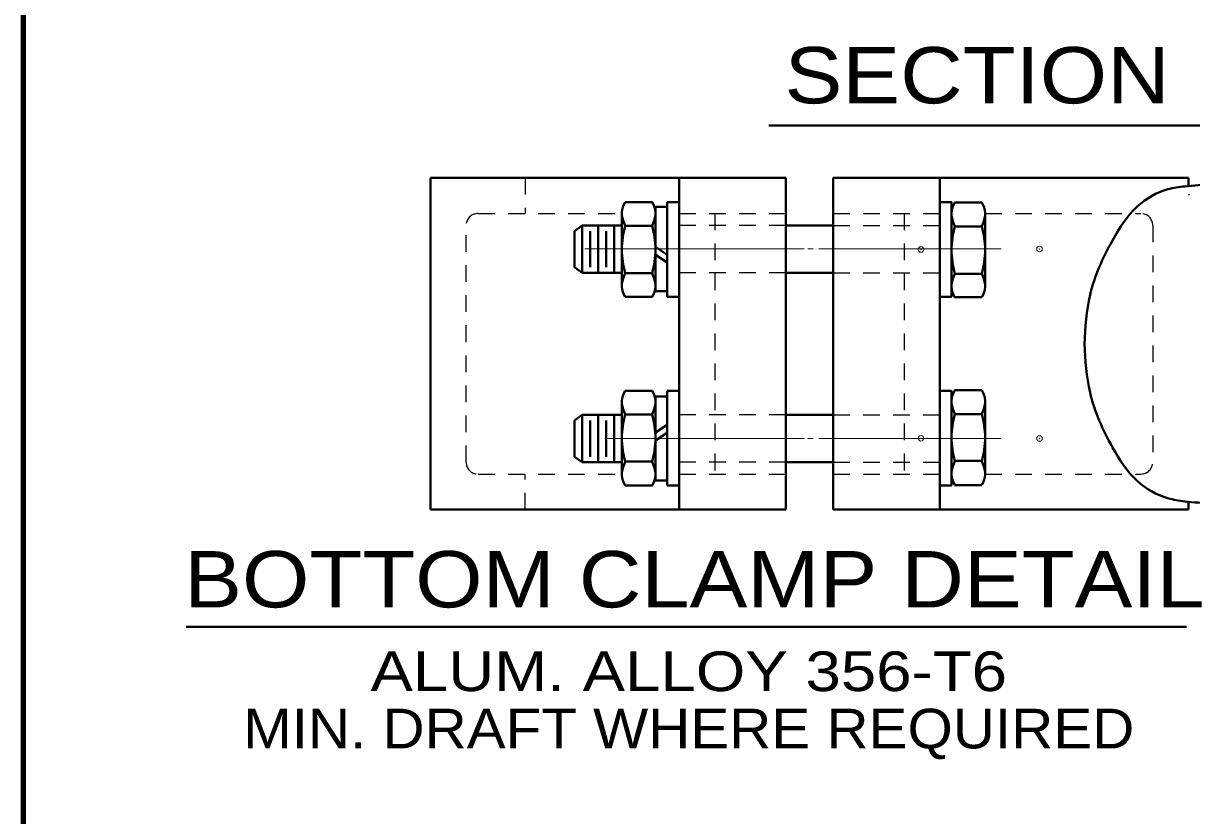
# Model space of a CAD drawing. Extents: x 312583 to 312854, y 144419 to 144597.
# Drawn here: x 312616.5 to 312648.02, y 144524.12 to 144545.49 of the extents above; entities that cross this region are included whole.
import ezdxf
from ezdxf.enums import TextEntityAlignment as Align

# ---------------------------------------------------------------- set-up
doc = ezdxf.new("R2010")
doc.units = 0
doc.header["$LTSCALE"] = 0.3
doc.header["$PDMODE"] = 32
doc.header["$PDSIZE"] = 0.15
doc.linetypes.add('SHORT_DASHED', pattern=[2.7, 1.5, -1.2])
doc.layers.add('1', color=7, linetype='Continuous', lineweight=35)
doc.layers.add('2', color=7, linetype='Continuous', lineweight=13)

msp = doc.modelspace()

# ---------------------------------------------------------------- linework, layer by layer
at = {"layer": '1', "lineweight": 40}
for p, q in [((312627.4877, 144536.8489), (312627.4877, 144541.3263)), ((312634.196, 144536.8489), (312634.196, 144541.3263)), ((312637.071, 144536.8489), (312637.071, 144541.3263)), ((312638.3513, 144536.8489), (312638.3513, 144541.3263)), ((312641.2263, 144536.8489), (312641.2263, 144541.3263)), ((312647.9347, 144541.1039), (312647.9347, 144541.3263)), ((312633.4753, 144540.6746), (312632.7393, 144540.6746)), ((312633.874, 144540.6746), (312633.874, 144538.1216)), ((312633.874, 144540.6746), (312634.196, 144540.6746)), ((312634.196, 144540.6746), (312634.196, 144538.1216)), ((312641.2263, 144538.1216), (312641.2263, 144540.6746)), ((312641.625, 144540.6593), (312642.361, 144540.6593)), ((312632.6473, 144540.3909), (312632.6473, 144539.4019)), ((312633.5597, 144540.3986), (312633.5597, 144540.5443)), ((312633.5597, 144540.5443), (312633.5597, 144538.2673)), ((312633.5597, 144540.5443), (312633.874, 144540.5443)), ((312633.5597, 144540.3986), (312633.5597, 144539.4096)), ((312641.5407, 144540.3833), (312641.5407, 144539.3943)), ((312642.453, 144540.3756), (312642.453, 144539.3943)), ((312632.6473, 144540.0459), (312631.5817, 144540.0459)), ((312632.011, 144540.0459), (312632.011, 144539.4019)), ((312632.4403, 144540.0459), (312632.4403, 144539.4019)), ((312633.4753, 144540.0306), (312632.7393, 144540.0306)), ((312638.3513, 144540.0459), (312637.071, 144540.0459)), ((312641.625, 144540.0153), (312642.361, 144540.0153)), ((312631.367, 144539.8926), (312631.367, 144539.4019)), ((312631.7963, 144539.8926), (312631.7963, 144539.4019)), ((312632.2257, 144539.8926), (312632.2257, 144539.4019)), ((312631.367, 144538.9189), (312631.367, 144539.4096)), ((312631.7963, 144538.9189), (312631.7963, 144539.4096)), ((312632.011, 144538.7656), (312632.011, 144539.4096)), ((312632.2257, 144538.9189), (312632.2257, 144539.4096)), ((312632.4403, 144538.7656), (312632.4403, 144539.4096)), ((312632.6473, 144538.3976), (312632.6473, 144539.4096)), ((312633.5597, 144539.4633), (312633.874, 144539.2486)), ((312633.5597, 144538.3976), (312633.5597, 144539.4096)), ((312641.5407, 144538.3823), (312641.5407, 144539.3943)), ((312642.453, 144538.3899), (312642.453, 144539.4019)), ((312633.5597, 144539.2486), (312633.874, 144539.0416)), ((312632.6473, 144538.7656), (312631.5817, 144538.7656)), ((312633.4677, 144538.7579), (312632.7393, 144538.7579)), ((312638.3513, 144538.7656), (312637.071, 144538.7656)), ((312641.6327, 144538.7426), (312642.361, 144538.7426)), ((312633.5597, 144538.2673), (312633.5597, 144538.3976)), ((312633.4753, 144538.1216), (312632.7393, 144538.1216)), ((312633.5597, 144538.2673), (312633.874, 144538.2673)), ((312633.874, 144538.1216), (312634.196, 144538.1216)), ((312641.5407, 144538.1216), (312641.2263, 144538.1216)), ((312641.625, 144538.1063), (312642.361, 144538.1063)), ((312627.4877, 144536.8489), (312627.4877, 144532.3793)), ((312634.196, 144536.8489), (312634.196, 144532.3793)), ((312637.071, 144536.8489), (312637.071, 144532.3793)), ((312638.3513, 144536.8489), (312638.3513, 144532.3793)), ((312641.2263, 144536.8489), (312641.2263, 144532.3793)), ((312633.4753, 144535.5839), (312632.7393, 144535.5839)), ((312633.874, 144535.5839), (312634.196, 144535.5839)), ((312633.874, 144533.0309), (312633.874, 144535.5839)), ((312634.196, 144533.0309), (312634.196, 144535.5839)), ((312641.5407, 144535.5839), (312641.2263, 144535.5839)), ((312641.2263, 144535.5839), (312641.2263, 144533.0309)), ((312641.625, 144535.5993), (312642.361, 144535.5993)), ((312632.6473, 144535.3003), (312632.6473, 144534.2883)), ((312633.5597, 144535.4306), (312633.5597, 144535.3079)), ((312633.5597, 144535.4306), (312633.874, 144535.4306)), ((312633.5597, 144533.1613), (312633.5597, 144535.4306)), ((312633.5597, 144535.3079), (312633.5597, 144534.2959)), ((312641.5407, 144535.3156), (312641.5407, 144534.3036)), ((312642.453, 144535.3156), (312642.453, 144534.3036)), ((312632.6473, 144534.9323), (312631.5817, 144534.9323)), ((312632.011, 144534.9323), (312632.011, 144534.2883)), ((312632.4403, 144534.9323), (312632.4403, 144534.2883)), ((312633.4677, 144534.9476), (312632.7393, 144534.9476)), ((312638.3513, 144534.9323), (312637.071, 144534.9323)), ((312641.6327, 144534.9553), (312642.361, 144534.9553)), ((312631.367, 144534.7866), (312631.367, 144534.2883)), ((312631.7963, 144534.7866), (312631.7963, 144534.2883)), ((312632.2257, 144534.7866), (312632.2257, 144534.2883)), ((312633.5597, 144534.4569), (312633.874, 144534.6639)), ((312631.367, 144533.8053), (312631.367, 144534.3036)), ((312631.7963, 144533.8053), (312631.7963, 144534.3036)), ((312632.011, 144533.6596), (312632.011, 144534.3036)), ((312632.2257, 144533.8053), (312632.2257, 144534.3036)), ((312632.4403, 144533.6596), (312632.4403, 144534.3036)), ((312632.6473, 144533.3146), (312632.6473, 144534.2959)), ((312633.5597, 144534.2423), (312633.874, 144534.4493)), ((312633.5597, 144533.3069), (312633.5597, 144534.2959)), ((312641.5407, 144533.3223), (312641.5407, 144534.3036)), ((312642.453, 144533.3223), (312642.453, 144534.3113)), ((312632.6473, 144533.6596), (312631.5817, 144533.6596)), ((312633.4753, 144533.6749), (312632.7393, 144533.6749)), ((312638.3513, 144533.6596), (312637.071, 144533.6596)), ((312641.625, 144533.6903), (312642.361, 144533.6903)), ((312633.5597, 144533.3069), (312633.5597, 144533.1613)), ((312633.4753, 144533.0309), (312632.7393, 144533.0309)), ((312633.5597, 144533.1613), (312633.874, 144533.1613)), ((312633.874, 144533.0309), (312634.196, 144533.0309)), ((312641.625, 144533.0386), (312642.361, 144533.0386)), ((312647.9347, 144532.5939), (312647.9347, 144532.3793))]:
    msp.add_line(p, q, dxfattribs=at)
at = {"layer": '1', "linetype": 'SHORT_DASHED', "lineweight": 25}
for p, q in [((312630.0407, 144541.3263), (312630.0407, 144540.3679)), ((312628.768, 144540.3679), (312632.6473, 144540.3679)), ((312634.196, 144540.3679), (312637.071, 144540.3679)), ((312635.1543, 144540.3679), (312635.1543, 144533.3376)), ((312638.3513, 144540.3679), (312641.2263, 144540.3679)), ((312640.268, 144540.3679), (312640.268, 144533.3376)), ((312642.453, 144540.3679), (312646.6543, 144540.3679)), ((312628.446, 144533.6596), (312628.446, 144540.0459)), ((312637.071, 144540.0459), (312634.196, 144540.0459)), ((312638.3513, 144540.0459), (312641.2263, 144540.0459)), ((312646.9763, 144540.0459), (312646.9763, 144533.6596)), ((312637.071, 144538.7656), (312634.196, 144538.7656)), ((312638.3513, 144538.7656), (312641.2263, 144538.7656)), ((312637.071, 144534.9323), (312634.196, 144534.9323)), ((312638.3513, 144534.9323), (312641.2263, 144534.9323)), ((312637.071, 144533.6596), (312634.196, 144533.6596)), ((312638.3513, 144533.6596), (312641.2263, 144533.6596)), ((312628.768, 144533.3376), (312632.6473, 144533.3376)), ((312630.0407, 144532.3793), (312630.0407, 144533.3376)), ((312634.196, 144533.3376), (312637.071, 144533.3376)), ((312638.3513, 144533.3376), (312641.2263, 144533.3376)), ((312642.453, 144533.3376), (312646.6543, 144533.3376))]:
    msp.add_line(p, q, dxfattribs=at)
at = {"layer": '1', "lineweight": 25}
msp.add_line((312647.9347, 144540.8586), (312647.9653, 144540.8893), dxfattribs=at)
at = {"layer": '1', "lineweight": 158}
msp.add_lwpolyline([(312616.5, 144423.1446), (312616.5, 144585.0846), (312849, 144585.0846)], dxfattribs=at)
at = {"layer": '1', "lineweight": 40}
for points in [[(312627.4877, 144541.3263), (312634.196, 144541.3263), (312637.071, 144541.3263)], [(312647.9347, 144541.3263), (312641.2263, 144541.3263), (312638.3513, 144541.3263)], [(312641.5407, 144538.1216), (312641.5407, 144540.6746), (312641.2263, 144540.6746)], [(312631.367, 144539.8926), (312631.5817, 144540.0459), (312631.5817, 144539.4019)], [(312631.367, 144538.9189), (312631.5817, 144538.7656), (312631.5817, 144539.4096)], [(312641.5407, 144535.5839), (312641.5407, 144533.0309), (312641.2263, 144533.0309)], [(312631.367, 144534.7866), (312631.5817, 144534.9323), (312631.5817, 144534.2883)], [(312631.367, 144533.8053), (312631.5817, 144533.6596), (312631.5817, 144534.3036)], [(312627.4877, 144532.3793), (312634.196, 144532.3793), (312637.071, 144532.3793)], [(312647.9347, 144532.3793), (312641.2263, 144532.3793), (312638.3513, 144532.3793)]]:
    msp.add_lwpolyline(points, dxfattribs=at)
for centre, radius, start, end in [((312633.1751, 144540.3759), 0.5262, 145.8703, 178.33743), ((312633.0301, 144540.3759), 0.5262, 1.66257, 34.1297), ((312642.0702, 144540.3631), 0.5262, 145.8703, 178.33743), ((312641.9253, 144540.3631), 0.5262, 1.66257, 34.1297), ((312634.1227, 144540.63), 1.5067, 191.77014, 203.36365), ((312632.0825, 144540.63), 1.5067, 336.63635, 348.22986), ((312643.0179, 144540.6172), 1.5067, 191.77014, 203.36365), ((312640.9776, 144540.6172), 1.5067, 336.63635, 348.22986), ((312635.366, 144539.3286), 2.7192, 164.99798, 178.595), ((312630.8392, 144539.3286), 2.7192, 1.405, 15.00202), ((312644.2612, 144539.3158), 2.7192, 164.99798, 178.595), ((312639.7343, 144539.3158), 2.7192, 1.405, 15.00202), ((312635.366, 144539.462), 2.7192, 181.405, 195.00202), ((312630.8392, 144539.462), 2.7192, 344.99798, 358.595), ((312644.2612, 144539.4492), 2.7192, 181.405, 195.00202), ((312639.7343, 144539.4492), 2.7192, 344.99798, 358.595), ((312634.1227, 144538.1606), 1.5067, 156.63635, 168.22986), ((312632.0825, 144538.1606), 1.5067, 11.77014, 23.36365), ((312643.0179, 144538.1478), 1.5067, 156.63635, 168.22986), ((312640.9776, 144538.1478), 1.5067, 11.77014, 23.36365), ((312633.1751, 144538.4147), 0.5262, 181.66257, 214.1297), ((312633.0301, 144538.4147), 0.5262, 325.8703, 358.33743), ((312642.0702, 144538.4019), 0.5262, 181.66257, 214.1297), ((312641.9253, 144538.4019), 0.5262, 325.8703, 358.33743), ((312633.1751, 144535.2883), 0.5262, 145.8703, 178.33743), ((312633.0301, 144535.2883), 0.5262, 1.66257, 34.1297), ((312642.0702, 144535.3011), 0.5262, 145.8703, 178.33743), ((312641.9253, 144535.3011), 0.5262, 1.66257, 34.1297), ((312634.1227, 144535.5424), 1.5067, 191.77014, 203.36365), ((312632.0825, 144535.5424), 1.5067, 336.63635, 348.22986), ((312643.0179, 144535.5552), 1.5067, 191.77014, 203.36365), ((312640.9776, 144535.5552), 1.5067, 336.63635, 348.22986), ((312635.366, 144534.241), 2.7192, 164.99798, 178.595), ((312630.8392, 144534.241), 2.7192, 1.405, 15.00202), ((312644.2612, 144534.2538), 2.7192, 164.99798, 178.595), ((312639.7343, 144534.2538), 2.7192, 1.405, 15.00202), ((312635.366, 144534.3744), 2.7192, 181.405, 195.00202), ((312630.8392, 144534.3744), 2.7192, 344.99798, 358.595), ((312644.2612, 144534.3871), 2.7192, 181.405, 195.00202), ((312639.7343, 144534.3871), 2.7192, 344.99798, 358.595), ((312634.1227, 144533.073), 1.5067, 156.63635, 168.22986), ((312632.0825, 144533.073), 1.5067, 11.77014, 23.36365), ((312643.0179, 144533.0858), 1.5067, 156.63635, 168.22986), ((312640.9776, 144533.0858), 1.5067, 11.77014, 23.36365), ((312633.1751, 144533.3271), 0.5262, 181.66257, 214.1297), ((312633.0301, 144533.3271), 0.5262, 325.8703, 358.33743), ((312642.0702, 144533.3398), 0.5262, 181.66257, 214.1297), ((312641.9253, 144533.3398), 0.5262, 325.8703, 358.33743)]:
    msp.add_arc(centre, radius, start, end, dxfattribs=at)
at = {"layer": '1', "linetype": 'SHORT_DASHED', "lineweight": 25}
for centre, start, end in [((312628.7654, 144540.0459), 90, 180), ((312646.6543, 144540.0459), 0, 90), ((312628.7654, 144533.657), 180, 270), ((312646.6543, 144533.657), 270, 0)]:
    msp.add_arc(centre, 0.3194, start, end, dxfattribs=at)
at = {"layer": '1', "lineweight": 40}
for points in [[(312648.571, 144541.1653), (312647.835, 144541.0963), (312647.3827, 144541.0196), (312646.5547, 144540.5519), (312645.8877, 144539.6396), (312645.282, 144538.1676), (312645.1287, 144536.8489)], [(312648.571, 144532.5403), (312647.835, 144532.6016), (312647.3827, 144532.6859), (312646.5547, 144533.1536), (312645.8877, 144534.0583), (312645.282, 144535.5379), (312645.1287, 144536.8489)]]:
    msp.add_spline(points, degree=3, dxfattribs=at)
at = {"layer": '2', "lineweight": 40}
for p, q in [((312636.6125, 144542.7369), (312652.0881, 144542.7369)), ((312620.8912, 144529.2129), (312647.8887, 144529.2129))]:
    msp.add_line(p, q, dxfattribs=at)
at = {"layer": '2'}
for p, q in [((312637.5693, 144539.4096), (312631.6507, 144539.4096)), ((312637.669, 144539.4096), (312637.8147, 144539.4096)), ((312637.9603, 144539.4096), (312642.8823, 144539.4096)), ((312637.5693, 144534.2959), (312632.1873, 144534.2959)), ((312637.669, 144534.2959), (312637.8147, 144534.2959)), ((312637.9603, 144534.2959), (312642.8823, 144534.2959))]:
    msp.add_line(p, q, dxfattribs=at)
for p in [(312640.7203, 144539.3943), (312643.9173, 144539.4096), (312640.7203, 144534.3036), (312643.9173, 144534.2959)]:
    msp.add_point(p, dxfattribs=at)

# ---------------------------------------------------------------- texts
at = {"layer": '2', "width": 1.15}
for s, p in [('SECTION B-B', (312637.0399, 144543.3362)), ('BOTTOM CLAMP DETAIL', (312620.8398, 144529.7405))]:
    msp.add_text(s, height=1.52, dxfattribs=at).set_placement(p)
at = {"layer": '2'}
for s, width, p in [('ALUM. ALLOY 356-T6', 1.2, (312634.4538, 144527.4825)), ('MIN. DRAFT WHERE REQUIRED', 1.1, (312634.4539, 144525.9372))]:
    msp.add_text(s, height=1.07, dxfattribs=dict(at, width=width)).set_placement(p, align=Align.CENTER)

doc.saveas('drawing.dxf')
